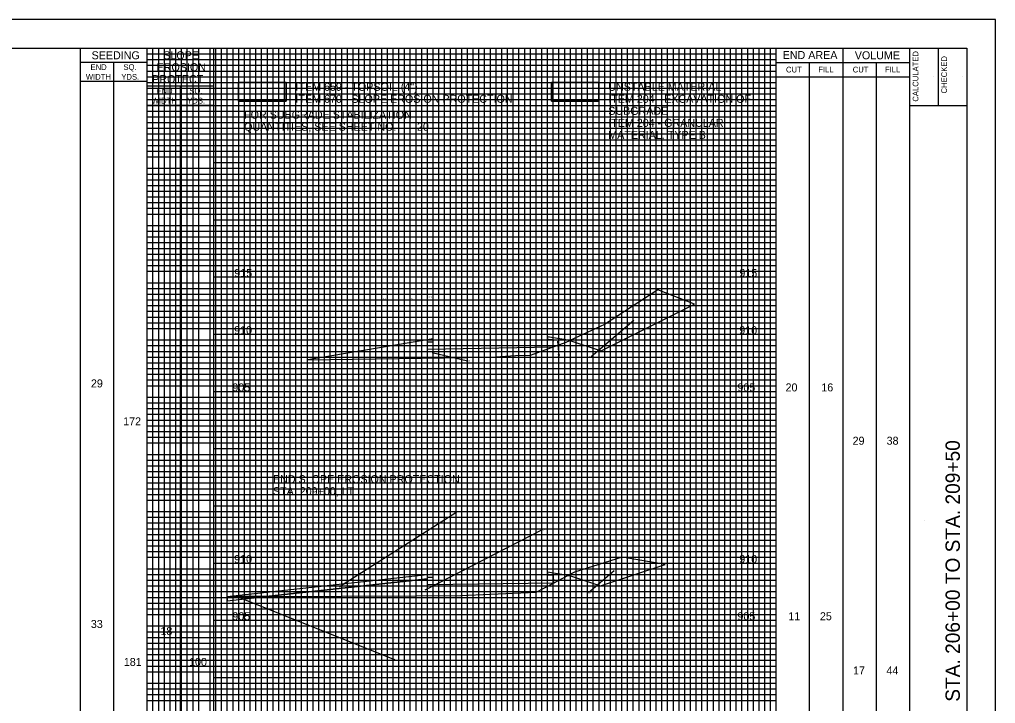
# Model space of a CAD drawing. Extents: x -73 to 160, y -2 to 1877.
# Drawn here: x 74.7 to 160, y 1542.7 to 1602.5 of the extents above; entities that cross this region are included whole.
import ezdxf

# ---------------------------------------------------------------- set-up
doc = ezdxf.new("R2010")
doc.units = 0
for name, color, linetype in [('DR_P_Flood_Boundary', 7, 'Continuous'), ('GK_Cells', 7, 'Continuous'), ('PV_P_Drive', 7, 'Continuous'), ('PV_P_EOP', 7, 'Continuous'), ('RD_X_Fence', 7, 'Continuous'), ('TX_X_5', 7, 'Continuous'), ('UT_P_Water_Cells', 7, 'Continuous'), ('XS_P_Pavt_Surface', 7, 'Continuous'), ('XS_P_Special_Benching', 7, 'Continuous'), ('XS_X_Ground_Line', 7, 'Continuous')]:
    doc.layers.add(name, color=color, linetype=linetype)

msp = doc.modelspace()

# ---------------------------------------------------------------- linework, layer by layer
at = {"layer": 'DR_P_Flood_Boundary'}
for p, q in [((95.832, 1495), (95.832, 1600)), ((100.832, 1495), (100.832, 1600)), ((105.832, 1495), (105.832, 1600)), ((110.832, 1495), (110.832, 1600)), ((115.832, 1495), (115.832, 1600)), ((120.832, 1495), (120.832, 1600)), ((125.832, 1495), (125.832, 1600)), ((130.832, 1495), (130.832, 1600)), ((135.832, 1495), (135.832, 1600)), ((85.832, 1595), (140.832, 1595)), ((91.665, 1590), (140.832, 1590)), ((91.665, 1585), (140.832, 1585)), ((91.665, 1580), (140.832, 1580)), ((91.665, 1575), (140.832, 1575)), ((91.665, 1570), (140.832, 1570)), ((91.665, 1565), (140.832, 1565)), ((91.665, 1560), (140.832, 1560)), ((91.665, 1555), (140.832, 1555)), ((91.665, 1550), (140.832, 1550)), ((91.665, 1545), (140.832, 1545))]:
    msp.add_line(p, q, dxfattribs=at)
at = {"layer": 'GK_Cells'}
for p, q in [((152.5, 1495), (152.5, 1600)), ((155, 1600), (155, 1595)), ((152.5, 1595), (157.5, 1595))]:
    msp.add_line(p, q, dxfattribs=at)
msp.add_lwpolyline([(0, 1600), (157.5, 1600), (157.5, 1495), (0, 1495)], close=True, dxfattribs=at)
at = {"layer": 'PV_P_Drive'}
msp.add_lwpolyline([(93.823, 1596.985), (97.964, 1596.985), (97.964, 1595.37), (93.823, 1595.37)], close=True, dxfattribs=at)
msp.add_lwpolyline([(93.823, 1595.37), (97.964, 1595.37), (97.964, 1596.985), (93.823, 1596.985), (93.823, 1595.37)], dxfattribs=at)
at = {"layer": 'PV_P_EOP'}
msp.add_lwpolyline([(121.172, 1596.985), (125.313, 1596.985), (125.313, 1595.37), (121.172, 1595.37)], close=True, dxfattribs=at)
msp.add_lwpolyline([(121.172, 1595.37), (125.313, 1595.37), (125.313, 1596.985), (121.172, 1596.985), (121.172, 1595.37)], dxfattribs=at)
at = {"layer": 'RD_X_Fence'}
for p, q in [((133.696, 1577.632), (130.466, 1578.866)), ((125.531, 1573.55), (133.696, 1577.632)), ((128.39, 1576.193), (124.66, 1573.008)), ((110.832, 1574.583), (99.885, 1572.758)), ((122.777, 1574.459), (120.832, 1574.783)), ((120.832, 1574.533), (121.332, 1574.543)), ((121.332, 1574.543), (121.267, 1573.875)), ((110.332, 1574.323), (110.832, 1574.333)), ((110.332, 1573.656), (110.332, 1574.323)), ((121.267, 1573.875), (110.332, 1573.656)), ((121.701, 1574.383), (121.827, 1573.134)), ((122.777, 1574.459), (125.531, 1573.55)), ((110.751, 1573.403), (113.841, 1572.661)), ((102.638, 1552.957), (112.806, 1559.417)), ((110.129, 1552.667), (120.394, 1557.923)), ((127.356, 1555.517), (123.179, 1554.216)), ((125.476, 1553), (131.131, 1554.885)), ((131.131, 1554.885), (127.356, 1555.517)), ((122.617, 1553.917), (120.832, 1554.214)), ((123.179, 1554.216), (122.617, 1553.917)), ((126.651, 1554.33), (124.417, 1552.392)), ((110.832, 1554.014), (93.076, 1552.067)), ((110.332, 1553.63), (96.215, 1552.082)), ((96.215, 1552.082), (110.332, 1553.63)), ((110.332, 1553.754), (110.832, 1553.764)), ((110.332, 1553.63), (110.332, 1553.754)), ((110.332, 1553.088), (110.332, 1553.63)), ((121.363, 1553.251), (110.332, 1553.088)), ((119.849, 1552.447), (121.363, 1553.251)), ((120.832, 1553.964), (121.332, 1553.974)), ((121.332, 1553.974), (121.363, 1553.251)), ((121.363, 1553.251), (122.617, 1553.917)), ((122.617, 1553.917), (122.832, 1553.881)), ((122.832, 1553.881), (125.476, 1553)), ((115.833, 1552.272), (119.849, 1552.447)), ((92.832, 1551.711), (96.215, 1552.082)), ((93.076, 1552.067), (92.832, 1552.041)), ((92.832, 1552.041), (92.832, 1551.711)), ((93.076, 1552.067), (96.215, 1552.082)), ((96.215, 1552.082), (93.076, 1552.067)), ((93.966, 1551.952), (107.451, 1546.575)), ((96.215, 1552.082), (109.332, 1552.141)), ((109.332, 1552.141), (113.241, 1552.159)), ((113.241, 1552.159), (115.833, 1552.272))]:
    msp.add_line(p, q, dxfattribs=at)
for points in [[(130.466, 1578.866), (125.81, 1575.833), (122.777, 1574.459)], [(110.832, 1574.333), (110.832, 1574.479), (110.832, 1574.583)], [(120.832, 1574.783), (120.832, 1574.679), (120.832, 1574.533)], [(99.885, 1572.758), (115.832, 1573.001), (118.044, 1573.149), (119.335, 1573.164), (121.267, 1573.875)], [(121.267, 1573.875), (122.447, 1574.309), (122.777, 1574.459)], [(120.832, 1554.214), (120.832, 1554.11), (120.832, 1553.964)], [(110.832, 1553.764), (110.832, 1553.91), (110.832, 1554.014)]]:
    msp.add_lwpolyline(points, dxfattribs=at)
at = {"layer": 'TX_X_5'}
msp.add_lwpolyline([(-10, 1492.5), (160, 1492.5), (160, 1602.5), (-10, 1602.5)], close=True, dxfattribs=at)
at = {"layer": 'UT_P_Water_Cells'}
for p, q in [((85.832, 1599.5), (140.832, 1599.5)), ((86.332, 1495), (86.332, 1600)), ((86.832, 1495), (86.832, 1600)), ((87.332, 1495), (87.332, 1600)), ((87.832, 1495), (87.832, 1600)), ((88.332, 1495), (88.332, 1600)), ((88.832, 1495), (88.832, 1600)), ((89.332, 1495), (89.332, 1600)), ((89.832, 1495), (89.832, 1600)), ((90.332, 1495), (90.332, 1600)), ((91.332, 1495), (91.332, 1600)), ((91.832, 1495), (91.832, 1600)), ((92.332, 1495), (92.332, 1600)), ((92.832, 1495), (92.832, 1600)), ((93.332, 1495), (93.332, 1600)), ((93.832, 1495), (93.832, 1600)), ((94.332, 1495), (94.332, 1600)), ((94.832, 1495), (94.832, 1600)), ((95.332, 1495), (95.332, 1600)), ((96.332, 1495), (96.332, 1600)), ((96.832, 1495), (96.832, 1600)), ((97.332, 1495), (97.332, 1600)), ((97.832, 1495), (97.832, 1600)), ((98.332, 1495), (98.332, 1600)), ((98.832, 1495), (98.832, 1600)), ((99.332, 1495), (99.332, 1600)), ((99.832, 1495), (99.832, 1600)), ((100.332, 1495), (100.332, 1600)), ((101.332, 1495), (101.332, 1600)), ((101.832, 1495), (101.832, 1600)), ((102.332, 1495), (102.332, 1600)), ((102.832, 1495), (102.832, 1600)), ((103.332, 1495), (103.332, 1600)), ((103.832, 1495), (103.832, 1600)), ((104.332, 1495), (104.332, 1600)), ((104.832, 1495), (104.832, 1600)), ((105.332, 1495), (105.332, 1600)), ((106.332, 1495), (106.332, 1600)), ((106.832, 1495), (106.832, 1600)), ((107.332, 1495), (107.332, 1600)), ((107.832, 1495), (107.832, 1600)), ((108.332, 1495), (108.332, 1600)), ((108.832, 1495), (108.832, 1600)), ((109.332, 1495), (109.332, 1600)), ((109.832, 1495), (109.832, 1600)), ((110.332, 1495), (110.332, 1600)), ((111.332, 1495), (111.332, 1600)), ((111.832, 1495), (111.832, 1600)), ((112.332, 1495), (112.332, 1600)), ((112.832, 1495), (112.832, 1600)), ((113.332, 1495), (113.332, 1600)), ((113.832, 1495), (113.832, 1600)), ((114.332, 1495), (114.332, 1600)), ((114.832, 1495), (114.832, 1600)), ((115.332, 1495), (115.332, 1600)), ((116.332, 1495), (116.332, 1600)), ((116.832, 1495), (116.832, 1600)), ((117.332, 1495), (117.332, 1600)), ((117.832, 1495), (117.832, 1600)), ((118.332, 1495), (118.332, 1600)), ((118.832, 1495), (118.832, 1600)), ((119.332, 1495), (119.332, 1600)), ((119.832, 1495), (119.832, 1600)), ((120.332, 1495), (120.332, 1600)), ((121.332, 1495), (121.332, 1600)), ((121.832, 1495), (121.832, 1600)), ((122.332, 1495), (122.332, 1600)), ((122.832, 1495), (122.832, 1600)), ((123.332, 1495), (123.332, 1600)), ((123.832, 1495), (123.832, 1600)), ((124.332, 1495), (124.332, 1600)), ((124.832, 1495), (124.832, 1600)), ((125.332, 1495), (125.332, 1600)), ((126.332, 1495), (126.332, 1600)), ((126.832, 1495), (126.832, 1600)), ((127.332, 1495), (127.332, 1600)), ((127.832, 1495), (127.832, 1600)), ((128.332, 1495), (128.332, 1600)), ((128.832, 1495), (128.832, 1600)), ((129.332, 1495), (129.332, 1600)), ((129.832, 1495), (129.832, 1600)), ((130.332, 1495), (130.332, 1600)), ((131.332, 1495), (131.332, 1600)), ((131.832, 1495), (131.832, 1600)), ((132.332, 1495), (132.332, 1600)), ((132.832, 1495), (132.832, 1600)), ((133.332, 1495), (133.332, 1600)), ((133.832, 1495), (133.832, 1600)), ((134.332, 1495), (134.332, 1600)), ((134.832, 1495), (134.832, 1600)), ((135.332, 1495), (135.332, 1600)), ((136.332, 1495), (136.332, 1600)), ((136.832, 1495), (136.832, 1600)), ((137.332, 1495), (137.332, 1600)), ((137.832, 1495), (137.832, 1600)), ((138.332, 1495), (138.332, 1600)), ((138.832, 1495), (138.832, 1600)), ((139.332, 1495), (139.332, 1600)), ((139.832, 1495), (139.832, 1600)), ((140.332, 1495), (140.332, 1600)), ((85.832, 1599), (140.832, 1599)), ((85.832, 1598.5), (140.832, 1598.5)), ((85.832, 1598), (140.832, 1598)), ((85.832, 1597.5), (140.832, 1597.5)), ((85.832, 1597), (140.832, 1597)), ((85.832, 1596.5), (140.832, 1596.5)), ((85.832, 1596), (140.832, 1596)), ((85.832, 1595.5), (140.832, 1595.5)), ((85.832, 1594.5), (140.832, 1594.5)), ((85.832, 1594), (140.832, 1594)), ((85.832, 1593.5), (140.832, 1593.5)), ((85.832, 1593), (140.832, 1593)), ((85.832, 1592.5), (140.832, 1592.5)), ((85.832, 1592), (140.832, 1592)), ((85.832, 1591.5), (140.832, 1591.5)), ((85.832, 1591), (140.832, 1591)), ((85.832, 1590.5), (140.832, 1590.5)), ((85.832, 1589.5), (140.832, 1589.5)), ((85.832, 1589), (140.832, 1589)), ((85.832, 1588.5), (140.832, 1588.5)), ((85.832, 1588), (140.832, 1588)), ((85.832, 1587.5), (140.832, 1587.5)), ((85.832, 1587), (140.832, 1587)), ((85.832, 1586.5), (140.832, 1586.5)), ((85.832, 1586), (140.832, 1586)), ((85.832, 1585.5), (140.832, 1585.5)), ((85.832, 1584.5), (140.832, 1584.5)), ((85.832, 1584), (140.832, 1584)), ((85.832, 1583.5), (140.832, 1583.5)), ((85.832, 1583), (140.832, 1583)), ((85.832, 1582.5), (140.832, 1582.5)), ((85.832, 1582), (140.832, 1582)), ((85.832, 1581.5), (140.832, 1581.5)), ((85.832, 1581), (140.832, 1581)), ((85.832, 1580.5), (140.832, 1580.5)), ((85.832, 1579.5), (140.832, 1579.5)), ((85.832, 1579), (140.832, 1579)), ((85.832, 1578.5), (140.832, 1578.5)), ((85.832, 1578), (140.832, 1578)), ((85.832, 1577.5), (140.832, 1577.5)), ((85.832, 1577), (140.832, 1577)), ((85.832, 1576.5), (140.832, 1576.5)), ((85.832, 1576), (140.832, 1576)), ((85.832, 1575.5), (140.832, 1575.5)), ((85.832, 1574.5), (140.832, 1574.5)), ((85.832, 1574), (140.832, 1574)), ((85.832, 1573.5), (140.832, 1573.5)), ((85.832, 1573), (140.832, 1573)), ((85.832, 1572.5), (140.832, 1572.5)), ((85.832, 1572), (140.832, 1572)), ((85.832, 1571.5), (140.832, 1571.5)), ((85.832, 1571), (140.832, 1571)), ((85.832, 1570.5), (140.832, 1570.5)), ((85.832, 1569.5), (140.832, 1569.5)), ((85.832, 1569), (140.832, 1569)), ((85.832, 1568.5), (140.832, 1568.5)), ((85.832, 1568), (140.832, 1568)), ((85.832, 1567.5), (140.832, 1567.5)), ((85.832, 1567), (140.832, 1567)), ((85.832, 1566.5), (140.832, 1566.5)), ((85.832, 1566), (140.832, 1566)), ((85.832, 1565.5), (140.832, 1565.5)), ((85.832, 1564.5), (140.832, 1564.5)), ((85.832, 1564), (140.832, 1564)), ((85.832, 1563.5), (140.832, 1563.5)), ((85.832, 1563), (140.832, 1563)), ((85.832, 1562.5), (140.832, 1562.5)), ((85.832, 1562), (140.832, 1562)), ((85.832, 1561.5), (140.832, 1561.5)), ((85.832, 1561), (140.832, 1561)), ((85.832, 1560.5), (140.832, 1560.5)), ((85.832, 1559.5), (140.832, 1559.5)), ((85.832, 1559), (140.832, 1559)), ((85.832, 1558.5), (140.832, 1558.5)), ((85.832, 1558), (140.832, 1558)), ((85.832, 1557.5), (140.832, 1557.5)), ((85.832, 1557), (140.832, 1557)), ((85.832, 1556.5), (140.832, 1556.5)), ((85.832, 1556), (140.832, 1556)), ((85.832, 1555.5), (140.832, 1555.5)), ((85.832, 1554.5), (140.832, 1554.5)), ((85.832, 1554), (140.832, 1554)), ((85.832, 1553.5), (140.832, 1553.5)), ((85.832, 1553), (140.832, 1553)), ((85.832, 1552.5), (140.832, 1552.5)), ((85.832, 1552), (140.832, 1552)), ((85.832, 1551.5), (140.832, 1551.5)), ((85.832, 1551), (140.832, 1551)), ((85.832, 1550.5), (140.832, 1550.5)), ((85.832, 1549.5), (140.832, 1549.5)), ((85.832, 1549), (140.832, 1549)), ((85.832, 1548.5), (140.832, 1548.5)), ((85.832, 1548), (140.832, 1548)), ((85.832, 1547.5), (140.832, 1547.5)), ((85.832, 1547), (140.832, 1547)), ((85.832, 1546.5), (140.832, 1546.5)), ((85.832, 1546), (140.832, 1546)), ((85.832, 1545.5), (140.832, 1545.5)), ((85.832, 1544.5), (140.832, 1544.5)), ((85.832, 1544), (140.832, 1544)), ((85.832, 1543.5), (140.832, 1543.5)), ((85.832, 1543), (140.832, 1543))]:
    msp.add_line(p, q, dxfattribs=at)
at = {"layer": 'XS_X_Ground_Line'}
for p, q in [((80, 1495), (80, 1600)), ((85.832, 1495), (85.832, 1600)), ((85.832, 1495), (85.832, 1600)), ((91.665, 1495), (91.665, 1600)), ((140.832, 1495), (140.832, 1600)), ((146.667, 1495), (146.667, 1600)), ((85.832, 1598.75), (80, 1598.75)), ((82.916, 1495), (82.916, 1598.75)), ((140.832, 1598.75), (152.5, 1598.75)), ((143.75, 1495), (143.75, 1598.75)), ((149.583, 1495), (149.583, 1598.75)), ((85.832, 1597.083), (80, 1597.083)), ((140.832, 1597.5), (152.5, 1597.5)), ((154.6, 1597.518), (154.6, 1597.518)), ((157.1, 1597.518), (157.1, 1597.518)), ((91.665, 1596.667), (85.832, 1596.667)), ((88.749, 1495), (88.749, 1596.667)), ((91.665, 1595), (85.832, 1595)), ((153.75, 1558.75), (153.75, 1558.75)), ((156.258, 1558.75), (156.258, 1558.75))]:
    msp.add_line(p, q, dxfattribs=at)

# ---------------------------------------------------------------- texts
at = {"layer": 'RD_X_Fence'}
for s, p in [('11.1', (102.564, 1577.888)), ('2.0', (106.433, 1577.981)), ('2.8', (108.742, 1578.024)), ('9.1', (110.44, 1578.156)), ('0.7', (121.674, 1573.064)), ('19.8', (124.479, 1572.938)), ('15.6', (113.658, 1572.591)), ('5.3', (112.646, 1559.347)), ('19.6', (120.2, 1557.853)), ('10.0', (124.225, 1552.322)), ('0.6', (107.285, 1546.505))]:
    msp.add_text(s, height=0.14, dxfattribs=at).set_placement(p)
at = {"layer": 'XS_P_Pavt_Surface'}
for s, p in [('915', (93.441, 1580)), ('915', (137.609, 1580)), ('910', (93.43, 1575)), ('910', (137.598, 1575)), ('29', (80.907, 1570.349)), ('905', (93.27, 1570)), ('905', (137.438, 1570)), ('20', (141.644, 1570)), ('16', (144.772, 1570)), ('172', (83.724, 1567.032)), ('29', (147.507, 1565.34)), ('38', (150.481, 1565.34)), ('END SLOPE EROSION PROTECTION', (96.822, 1561.981)), ('STA. 209+00, LT.', (96.822, 1560.931)), ('910', (93.43, 1555)), ('910', (137.598, 1555)), ('905', (93.27, 1550)), ('905', (137.438, 1550)), ('11', (141.892, 1550)), ('25', (144.648, 1550)), ('33', (80.899, 1549.323)), ('18', (86.98, 1548.704)), ('181', (83.781, 1546.006)), ('100', (89.487, 1546.006)), ('17', (147.546, 1545.26)), ('44', (150.467, 1545.26))]:
    msp.add_text(s, height=0.7, dxfattribs=at).set_placement(p)
at = {"layer": 'XS_P_Special_Benching'}
for s, p in [('ITEM 659 - TOPSOIL (4")', (98.791, 1596.271)), ('UNSTABLE MATERIAL', (126.141, 1596.271)), ('ITEM 670 - SLOPE EROSION PROTECTION', (98.791, 1595.221)), ('ITEM 204 - EXCAVATION OF', (126.141, 1595.221)), ('FOR SUBGRADE STABILIZATION', (94.299, 1593.83)), ('SUBGRADE', (126.141, 1594.171)), ('QUANTITIES, SEE SHEET NO.', (94.299, 1592.78)), ('20', (109.417, 1592.78)), ('ITEM 204 - GRANULAR', (126.141, 1593.121)), ('MATERIAL, TYPE B', (126.141, 1592.071))]:
    msp.add_text(s, height=0.7, dxfattribs=at).set_placement(p)
at = {"layer": 'XS_X_Ground_Line'}
for s, height, p in [('SEEDING', 0.7, (80.964, 1599.025)), ('SLOPE', 0.7, (87.228, 1599.025)), ('END AREA', 0.7, (141.394, 1599.047)), ('VOLUME', 0.7, (147.698, 1599.025)), ('END', 0.5, (80.87, 1598.092)), ('SQ.', 0.5, (83.748, 1598.092)), ('EROSION', 0.7, (86.649, 1597.983)), ('WIDTH', 0.5, (80.462, 1597.242)), ('YDS.', 0.5, (83.563, 1597.242)), ('PROTECT.', 0.7, (86.26, 1596.942)), ('CUT', 0.5, (141.683, 1597.875)), ('FILL', 0.5, (144.502, 1597.875)), ('CUT', 0.5, (147.517, 1597.875)), ('FILL', 0.5, (150.335, 1597.875)), ('END', 0.5, (86.631, 1596.008)), ('SQ.', 0.5, (89.51, 1596.008)), ('WIDTH', 0.5, (86.224, 1595.158)), ('YDS.', 0.5, (89.325, 1595.158))]:
    msp.add_text(s, height=height, dxfattribs=at).set_placement(p)
for s, height, p in [('CALCULATED', 0.5, (153.262, 1595.323)), ('CHECKED', 0.5, (155.762, 1596.04)), ('STA. 206+00 TO STA. 209+50', 1.25, (156.883, 1542.879))]:
    msp.add_text(s, height=height, rotation=90, dxfattribs=at).set_placement(p)

doc.saveas('drawing.dxf')
